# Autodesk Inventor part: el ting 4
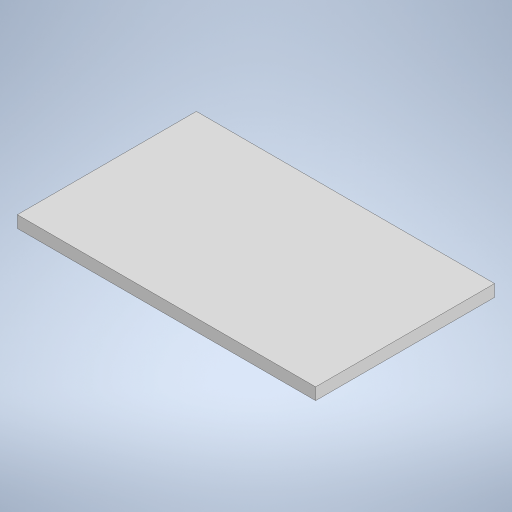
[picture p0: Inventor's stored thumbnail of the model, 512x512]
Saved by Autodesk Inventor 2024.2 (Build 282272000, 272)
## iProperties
Created: 2024-05
Part Number: el ting 4
Material: Generic
Document SubType Name: Modeling
Designer: Karsten
Density: 1 g/cm^3
Appearance: Default
Author: Karsten
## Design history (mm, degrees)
sketch "Sketch1"
  geometry: L1 (0, 0)-(50, 0); L2 (50, 0)-(50, -30); L3 (50, -30)-(0, -30); L4 (0, -30)-(0, 0)
  constraints: 8 end point, 2 parallel, 1 horizontal, 1 perpendicular
  dimensions: "d0" = 50 distance of L2.end L3.end; "d1" = 30 distance of L1.end L2.end
extrude "Extrusion1" new body sketch "Sketch1" distance "d2" = 2; taper "d3" = 0 deg
body "Solid1"
